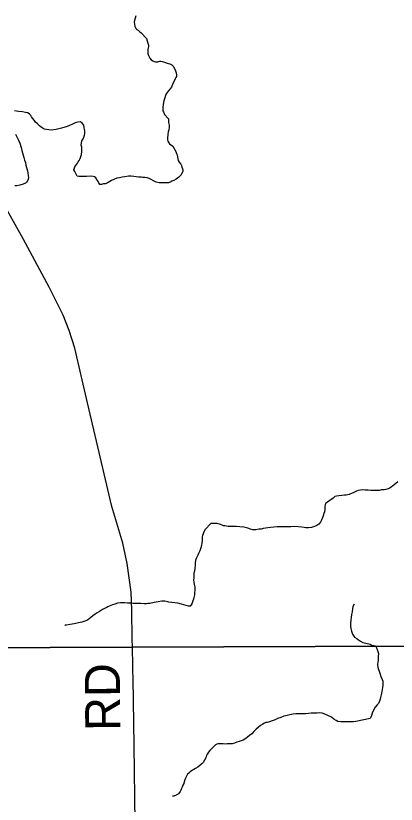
# Model space of a CAD drawing. Extents: x 0 to 34, y 0 to 22.
# Drawn here: x 3.225 to 3.841, y 15.108 to 16.386 of the extents above; entities that cross this region are included whole.
import ezdxf

# ---------------------------------------------------------------- set-up
doc = ezdxf.new("R2010")
doc.units = 0
for name, color, linetype in [('GM_X_Corporation', 7, 'Continuous'), ('GM_X_Minor_River', 7, 'Continuous'), ('GM_X_Township_Road', 7, 'Continuous'), ('GM_X_Township_Road_Text', 7, 'Continuous')]:
    doc.layers.add(name, color=color, linetype=linetype)

msp = doc.modelspace()

# ---------------------------------------------------------------- linework, layer by layer
at = {"layer": 'GM_X_Corporation'}
msp.add_lwpolyline([(2.1, 20.3879), (2.1, 15.3574), (2.6127, 15.3592), (3.4135, 15.3624), (4.1534, 15.3654), (4.1554, 15.3654), (5.1944, 15.3696), (5.8313, 15.3671), (6.0415, 15.3685), (7.1072, 15.3824), (7.0838, 16.6084)], dxfattribs=at)
msp.add_lwpolyline([(2.1, 15.3574), (2.1, 14.1), (7.1335, 14.1), (7.1269, 14.4049), (7.1267, 14.4123), (7.1215, 14.6514), (7.118, 14.8105), (7.1072, 15.3824), (6.0415, 15.3685), (5.8313, 15.3671), (5.1944, 15.3696), (4.1554, 15.3654), (4.1534, 15.3654), (3.4135, 15.3624), (2.6127, 15.3592)], close=True, dxfattribs=at)
at = {"layer": 'GM_X_Minor_River'}
for points in [[(3.4192, 16.3861), (3.418, 16.3823), (3.4168, 16.3785), (3.4164, 16.3758), (3.4167, 16.3724), (3.4175, 16.369), (3.4189, 16.3655), (3.4208, 16.3636), (3.4227, 16.3628), (3.4257, 16.3601), (3.428, 16.3582), (3.4362, 16.349), (3.4373, 16.3455), (3.4388, 16.3417), (3.4395, 16.3383), (3.4395, 16.336), (3.4391, 16.3341), (3.4387, 16.3311), (3.4383, 16.328), (3.4386, 16.325), (3.4397, 16.3216), (3.4416, 16.3174), (3.4442, 16.3147), (3.4464, 16.3131), (3.4487, 16.312), (3.451, 16.3112), (3.4529, 16.3111), (3.4548, 16.3115), (3.4578, 16.3126), (3.4597, 16.3126), (3.462, 16.3118), (3.4654, 16.311), (3.4696, 16.3094), (3.4741, 16.3082), (3.4775, 16.3067), (3.4798, 16.3044), (3.4816, 16.3005), (3.4835, 16.2967), (3.4846, 16.2933)], [(3.4846, 16.2933), (3.4849, 16.2899), (3.4849, 16.2876), (3.4841, 16.2857), (3.483, 16.2838), (3.4814, 16.28), (3.4791, 16.2762), (3.4767, 16.2702), (3.4713, 16.2638), (3.4682, 16.2596), (3.4671, 16.2566), (3.4659, 16.2528), (3.4643, 16.2483), (3.4635, 16.2422), (3.4626, 16.2373), (3.4626, 16.2339), (3.463, 16.232), (3.4637, 16.2301), (3.4655, 16.2262), (3.4719, 16.2189), (3.4722, 16.2128), (3.4729, 16.2087), (3.4733, 16.2056), (3.4725, 16.2011), (3.4717, 16.1976), (3.4709, 16.1935), (3.4704, 16.1878), (3.4704, 16.1847), (3.4707, 16.1828), (3.4737, 16.1786), (3.479, 16.1748), (3.4838, 16.166), (3.4849, 16.1625), (3.486, 16.1606), (3.4864, 16.1568), (3.4871, 16.1538), (3.4878, 16.1511), (3.4893, 16.1484), (3.4919, 16.1453), (3.4931, 16.1434), (3.4938, 16.1407), (3.4949, 16.1381), (3.4953, 16.1362), (3.4952, 16.1343), (3.4925, 16.1282), (3.4886, 16.1241), (3.4844, 16.1211), (3.4806, 16.1189), (3.4775, 16.1178), (3.4756, 16.117), (3.4722, 16.1152), (3.457, 16.1153), (3.4521, 16.1165), (3.4479, 16.1185), (3.4441, 16.1204), (3.4407, 16.122), (3.4373, 16.1232), (3.4339, 16.1236), (3.4305, 16.124), (3.4278, 16.1244), (3.424, 16.1245), (3.4199, 16.1249), (3.4157, 16.1253), (3.4115, 16.1258), (3.4073, 16.1258), (3.4012, 16.1251), (3.397, 16.1244), (3.3928, 16.1233), (3.3883, 16.1226), (3.3837, 16.1208), (3.3795, 16.1189), (3.3745, 16.1159), (3.3699, 16.1137), (3.3669, 16.1134), (3.3634, 16.1126), (3.3608, 16.1127), (3.3589, 16.115), (3.3571, 16.1192), (3.3544, 16.123), (3.3522, 16.1249), (3.3499, 16.1257), (3.3454, 16.1258), (3.3389, 16.1255), (3.3321, 16.1256), (3.3267, 16.1256), (3.3241, 16.126), (3.3204, 16.1337), (3.3189, 16.1364), (3.3205, 16.1409), (3.3232, 16.1451), (3.3247, 16.1469), (3.3259, 16.1492), (3.3274, 16.1515), (3.329, 16.1545), (3.3302, 16.1579), (3.3313, 16.1609), (3.3314, 16.1662), (3.3315, 16.1731), (3.3304, 16.1761), (3.3316, 16.183), (3.3335, 16.1864)], [(3.3335, 16.1864), (3.3347, 16.1894), (3.3359, 16.1924), (3.3363, 16.1951), (3.3363, 16.1977), (3.3364, 16.1996), (3.336, 16.2015), (3.3353, 16.205), (3.3346, 16.2084), (3.3319, 16.2119), (3.3297, 16.2138), (3.3251, 16.2135), (3.3209, 16.2124), (3.3156, 16.2098), (3.3079, 16.2064), (3.2988, 16.2039), (3.29, 16.2017), (3.282, 16.2007), (3.2706, 16.2019), (3.2687, 16.2031), (3.2657, 16.2054), (3.2631, 16.2077), (3.2597, 16.2108), (3.2567, 16.2135), (3.2545, 16.2166), (3.2522, 16.2196), (3.2503, 16.2223), (3.2492, 16.2242), (3.247, 16.2265), (3.2443, 16.2285), (3.2402, 16.2293), (3.2356, 16.2301), (3.2292, 16.2309), (3.2223, 16.2318)], [(3.2242, 16.1941), (3.2264, 16.1895), (3.229, 16.1842), (3.2312, 16.1792), (3.2334, 16.1723), (3.2345, 16.1678), (3.2378, 16.1563), (3.2389, 16.1521), (3.2403, 16.1479), (3.241, 16.1437), (3.2421, 16.1399), (3.2432, 16.1365), (3.2436, 16.1346), (3.2443, 16.1312), (3.2446, 16.127), (3.245, 16.1239), (3.2446, 16.1213), (3.2438, 16.1182), (3.2422, 16.116), (3.2403, 16.1145), (3.2365, 16.113), (3.2311, 16.1116), (3.2262, 16.1105), (3.2228, 16.1105)], [(3.8435, 15.6303), (3.8404, 15.628), (3.8377, 15.6254), (3.835, 15.6235), (3.8331, 15.6224), (3.8312, 15.6209), (3.8277, 15.6191), (3.8239, 15.618), (3.8213, 15.6176), (3.819, 15.6173), (3.8163, 15.6173), (3.8136, 15.6166), (3.8102, 15.6162), (3.8064, 15.6163), (3.8038, 15.6163), (3.8, 15.6164), (3.7954, 15.6168), (3.7905, 15.6172), (3.7863, 15.6173), (3.7829, 15.6169), (3.7794, 15.6166), (3.7764, 15.6151), (3.771, 15.6125), (3.7668, 15.611), (3.7645, 15.6099), (3.7619, 15.6092), (3.7596, 15.6088), (3.7569, 15.6089), (3.7527, 15.6085), (3.7482, 15.6078), (3.744, 15.6071), (3.7413, 15.6068), (3.7386, 15.6042), (3.7336, 15.6004), (3.7298, 15.5974), (3.7271, 15.5959), (3.7259, 15.5937), (3.7255, 15.5895), (3.7255, 15.5857), (3.7247, 15.5819), (3.7239, 15.5789), (3.7227, 15.5755), (3.7223, 15.5736), (3.7195, 15.5675), (3.7184, 15.5652), (3.7153, 15.5619), (3.7122, 15.5596), (3.7088, 15.5578), (3.7038, 15.5567), (3.6989, 15.556), (3.6943, 15.556), (3.6917, 15.5564), (3.6879, 15.5572), (3.6825, 15.5577), (3.6761, 15.5578), (3.67, 15.5575), (3.6647, 15.5575), (3.6601, 15.5576), (3.6578, 15.5576), (3.6544, 15.5576), (3.6483, 15.5577), (3.6426, 15.557), (3.6373, 15.5567), (3.6331, 15.556), (3.6293, 15.5553), (3.6255, 15.5546), (3.6221, 15.5538), (3.6183, 15.5535), (3.6133, 15.5524), (3.6084, 15.5525), (3.6046, 15.5537), (3.6008, 15.5556), (3.594, 15.5568), (3.5875, 15.5577), (3.5814, 15.5581), (3.5754, 15.5582), (3.5685, 15.5583), (3.5632, 15.5591), (3.5613, 15.5591), (3.559, 15.5603)], [(3.559, 15.5603), (3.5564, 15.5615), (3.5511, 15.5627), (3.5469, 15.5627), (3.5435, 15.5628), (3.5404, 15.5628), (3.5312, 15.553), (3.5293, 15.5492), (3.5281, 15.5462), (3.5269, 15.5432), (3.5265, 15.5413), (3.5265, 15.5386), (3.5264, 15.5356), (3.526, 15.5318), (3.5256, 15.5272), (3.5244, 15.5235), (3.5228, 15.5185), (3.5208, 15.5144), (3.5193, 15.5114), (3.5177, 15.5083), (3.5166, 15.5064), (3.5158, 15.503), (3.5153, 15.4992), (3.5153, 15.4947), (3.5145, 15.4905), (3.514, 15.4859), (3.5132, 15.4825), (3.5128, 15.4803), (3.5128, 15.478), (3.5128, 15.4749), (3.5127, 15.4715), (3.5131, 15.4673), (3.5134, 15.4647), (3.5141, 15.4616), (3.5145, 15.4597), (3.5148, 15.4551), (3.5144, 15.4506), (3.514, 15.4472), (3.5132, 15.443), (3.5124, 15.44), (3.5116, 15.4373), (3.51, 15.4328), (3.5069, 15.429), (3.5046, 15.4287), (3.5008, 15.4298), (3.4933, 15.4322), (3.4872, 15.4338), (3.4728, 15.4355), (3.4709, 15.4359), (3.4663, 15.4371), (3.4614, 15.4368), (3.4553, 15.4361), (3.4488, 15.4346), (3.4416, 15.4332), (3.4385, 15.4332), (3.4362, 15.4329), (3.4324, 15.4329), (3.4271, 15.433), (3.4207, 15.4331), (3.415, 15.4331), (3.4104, 15.4336), (3.4074, 15.4336), (3.4055, 15.4336), (3.4013, 15.4341), (3.3979, 15.4345), (3.3941, 15.4342), (3.3895, 15.4335), (3.3849, 15.4324), (3.3815, 15.4313), (3.3784, 15.4302), (3.3757, 15.4287), (3.3735, 15.4276), (3.3708, 15.4261), (3.3685, 15.4253), (3.365, 15.4235), (3.3601, 15.4205), (3.3562, 15.4183), (3.3532, 15.416), (3.3493, 15.413), (3.3463, 15.4108), (3.3432, 15.4078), (3.3397, 15.4059), (3.3363, 15.4044), (3.3317, 15.403), (3.326, 15.4019), (3.3191, 15.4005), (3.3127, 15.399), (3.307, 15.3983), (3.3051, 15.398), (3.3047, 15.398), (3.3043, 15.3976)], [(3.7727, 15.4321), (3.7726, 15.4319), (3.7707, 15.4282), (3.7699, 15.4244), (3.7695, 15.4198), (3.7686, 15.4153), (3.7678, 15.4107), (3.7674, 15.4062), (3.767, 15.4012), (3.7669, 15.3963), (3.7672, 15.3925), (3.7683, 15.3883), (3.7702, 15.3837), (3.7731, 15.3787), (3.7773, 15.3764), (3.7796, 15.3745), (3.783, 15.3721), (3.7871, 15.3702), (3.7985, 15.3674), (3.8015, 15.3658), (3.8045, 15.365), (3.8072, 15.3646), (3.8091, 15.3612), (3.8105, 15.357), (3.812, 15.3524), (3.8119, 15.3475), (3.8119, 15.3456), (3.8115, 15.3414), (3.8106, 15.3349), (3.8106, 15.333), (3.811, 15.33), (3.8124, 15.3262), (3.8135, 15.3235), (3.8146, 15.3205), (3.8161, 15.3147), (3.8179, 15.3102), (3.819, 15.3071), (3.8194, 15.3041), (3.819, 15.3006), (3.8185, 15.2968), (3.8177, 15.2908), (3.8165, 15.2851), (3.8157, 15.2809), (3.8149, 15.2779), (3.8137, 15.2749), (3.8121, 15.2711), (3.8098, 15.2688), (3.8068, 15.2651), (3.8036, 15.2594), (3.8021, 15.2556), (3.8009, 15.2514), (3.7997, 15.2492), (3.7986, 15.2469), (3.7757, 15.2422), (3.7719, 15.2415), (3.7677, 15.2412), (3.7624, 15.2413), (3.7567, 15.2413), (3.751, 15.2414), (3.7464, 15.2422), (3.7434, 15.2438), (3.74, 15.2457), (3.7362, 15.2488), (3.7302, 15.2519), (3.7253, 15.2539), (3.7211, 15.2554), (3.7173, 15.2559), (3.7131, 15.2555), (3.7082, 15.2552), (3.7032, 15.2553), (3.6987, 15.2549), (3.6937, 15.2546), (3.6884, 15.2543), (3.6838, 15.2543), (3.6785, 15.2544), (3.674, 15.2541), (3.6686, 15.253), (3.664, 15.2519), (3.6591, 15.2505), (3.6541, 15.2486), (3.6488, 15.2468), (3.6446, 15.2449), (3.64, 15.2431), (3.6354, 15.2412), (3.6316, 15.2405), (3.6297, 15.2402), (3.6274, 15.2394), (3.6251, 15.2376), (3.6209, 15.2353), (3.6171, 15.2323), (3.614, 15.2297), (3.6105, 15.226), (3.607, 15.2222), (3.6032, 15.2192), (3.6001, 15.2166), (3.5971, 15.2143), (3.5932, 15.2117), (3.5867, 15.2095)], [(3.5867, 15.2095), (3.5829, 15.2084), (3.5791, 15.2069), (3.5749, 15.2058), (3.5715, 15.2055), (3.5669, 15.2056), (3.5643, 15.2052), (3.5605, 15.2056), (3.5559, 15.2057), (3.5525, 15.2057), (3.5502, 15.2054), (3.5479, 15.2039), (3.5456, 15.2016), (3.5421, 15.1983), (3.5391, 15.1949), (3.5367, 15.1922), (3.5352, 15.1896), (3.5336, 15.1873), (3.5325, 15.1832), (3.5305, 15.179), (3.5282, 15.1756), (3.5263, 15.1741), (3.5228, 15.1704), (3.5197, 15.1677), (3.5159, 15.1659), (3.5132, 15.1644), (3.5109, 15.1629), (3.5071, 15.1603), (3.5052, 15.1584), (3.5029, 15.1565), (3.5013, 15.1535), (3.4997, 15.1501), (3.4986, 15.1475), (3.4974, 15.1444), (3.4966, 15.1414), (3.4954, 15.1388), (3.4942, 15.1353), (3.4927, 15.1323), (3.4919, 15.1304), (3.4907, 15.1286), (3.488, 15.1248), (3.4842, 15.1225), (3.4808, 15.1211), (3.4785, 15.1211), (3.4785, 15.1207), (3.4785, 15.1211)]]:
    msp.add_lwpolyline(points, dxfattribs=at)
at = {"layer": 'GM_X_Township_Road'}
for points in [[(3.4143, 15.3325), (3.4137, 15.3619), (3.4134, 15.376), (3.4125, 15.4223), (3.4115, 15.4516), (3.4053, 15.4979), (3.3979, 15.531), (3.3803, 15.5903), (3.3406, 15.7584), (3.3205, 15.8469), (3.3112, 15.8759), (3.3014, 15.9006), (3.2789, 15.9459), (3.2368, 16.0243), (3.2004, 16.089), (3.1831, 16.1248), (3.1751, 16.1461), (3.1744, 16.1479)], [(3.4261, 14.6004), (3.4265, 14.6214), (3.4221, 14.8063), (3.4198, 14.9522), (3.4164, 15.2028), (3.4147, 15.3118), (3.4144, 15.3246), (3.4143, 15.3325)]]:
    msp.add_lwpolyline(points, dxfattribs=at)

# ---------------------------------------------------------------- texts
at = {"layer": 'GM_X_Township_Road_Text'}
msp.add_text('RD', height=0.05682, rotation=90.4937, dxfattribs=at).set_placement((3.394, 15.2269))

doc.saveas('drawing.dxf')
